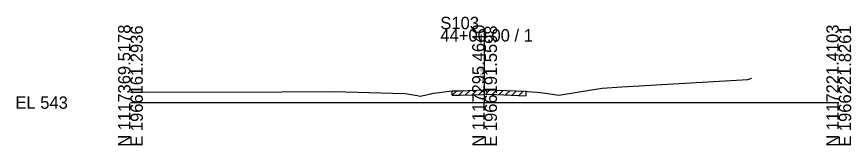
# Model space of a CAD drawing. Extents: x -26 to 163, y -10 to 45020.
# Drawn here: x -25.7 to 162.8, y 3990.3 to 4019.5 of the extents above; entities that cross this region are included whole.
import ezdxf

# ---------------------------------------------------------------- set-up
doc = ezdxf.new("R2010")
doc.units = 0
for name, color, linetype in [('RD_GPK_XS_Cell', 7, 'Continuous'), ('RD_XS_ExGround', 7, 'Continuous'), ('RD_XS_ExPaveRet', 7, 'Continuous'), ('RD_XS_TX_Elev_EX', 7, 'Continuous')]:
    doc.layers.add(name, color=color, linetype=linetype)

msp = doc.modelspace()

# ---------------------------------------------------------------- linework, layer by layer
at = {"layer": 'RD_GPK_XS_Cell'}
for p, q in [((80, 4000), (80, 4016.65)), ((0, 4000), (80, 4000)), ((80, 4000), (160, 4000))]:
    msp.add_line(p, q, dxfattribs=at)
at = {"layer": 'RD_XS_ExGround'}
for p, q in [((111, 4003.59), (139.48, 4005.23)), ((139.48, 4005.23), (140.36, 4005.55)), ((69.16, 4002.2), (72.71, 4002.67)), ((72.71, 4002.67), (74.52, 4002.7)), ((74.52, 4002.7), (80, 4002.87)), ((80, 4002.87), (80.8, 4002.89)), ((80.8, 4002.89), (82.66, 4002.82)), ((82.66, 4002.82), (89.29, 4002.56)), ((89.29, 4002.56), (89.7, 4002.52)), ((96.8, 4001.68), (104.64, 4002.97)), ((104.64, 4002.97), (106.54, 4003.28)), ((106.54, 4003.28), (111, 4003.59)), ((0, 4002.33), (2.58, 4002.37)), ((2.58, 4002.37), (34.23, 4002.41)), ((34.23, 4002.41), (45.93, 4002.51)), ((45.93, 4002.51), (59.24, 4002.13)), ((59.24, 4002.13), (62.03, 4002.09)), ((62.03, 4002.09), (64.74, 4001.62)), ((64.74, 4001.62), (65.44, 4001.44)), ((65.44, 4001.44), (67.52, 4001.94)), ((67.52, 4001.94), (68.08, 4002.07)), ((68.08, 4002.07), (69.16, 4002.2)), ((89.7, 4002.52), (91.9, 4002.34)), ((91.9, 4002.34), (93.25, 4002.19)), ((93.25, 4002.19), (96.8, 4001.68))]:
    msp.add_line(p, q, dxfattribs=at)
at = {"layer": 'RD_XS_ExPaveRet'}
for p, q in [((72.71, 4001.67), (73.73, 4002.69)), ((72.71, 4001.67), (72.71, 4002.67)), ((74.21, 4001.7), (75.24, 4002.72)), ((75.71, 4001.74), (76.75, 4002.77)), ((77.21, 4001.78), (78.25, 4002.81)), ((78.71, 4001.83), (79.75, 4002.86)), ((80.21, 4001.87), (81.22, 4002.88)), ((81.71, 4001.86), (82.68, 4002.82)), ((83.21, 4001.8), (84.18, 4002.76)), ((84.71, 4001.74), (85.68, 4002.7)), ((86.21, 4001.68), (87.18, 4002.65)), ((87.71, 4001.62), (88.68, 4002.59)), ((89.29, 4002.56), (89.29, 4001.56)), ((72.71, 4001.67), (74.52, 4001.7)), ((74.52, 4001.7), (80, 4001.87)), ((80, 4001.87), (80.8, 4001.89)), ((80.8, 4001.89), (82.66, 4001.82)), ((82.66, 4001.82), (89.29, 4001.56))]:
    msp.add_line(p, q, dxfattribs=at)

# ---------------------------------------------------------------- texts
at = {"layer": 'RD_GPK_XS_Cell'}
for s, p in [('S103', (70, 4016.65)), ('44+00.00 / 1', (70, 4013.85)), ('EL 543', (-26, 3998.6))]:
    msp.add_text(s, height=2.8, dxfattribs=at).set_placement(p)
for s, p in [('N 1117369.5178', (0, 3990)), ('E 1966161.2936', (2.8, 3990)), ('N 1117295.4640', (80, 3990)), ('E 1966191.5598', (82.8, 3990)), ('N 1117221.4103', (160, 3990)), ('E 1966221.8261', (162.8, 3990))]:
    msp.add_text(s, height=2.8, rotation=90, dxfattribs=at).set_placement(p)
at = {"layer": 'RD_XS_TX_Elev_EX'}
msp.add_text('545.87', height=0.8, rotation=90, dxfattribs=at).set_placement((79.9, 4004.87))

doc.saveas('drawing.dxf')
